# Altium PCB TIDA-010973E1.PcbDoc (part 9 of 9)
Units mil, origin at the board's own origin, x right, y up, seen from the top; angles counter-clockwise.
Board outline 5166 x 3669 mil, 8 copper layers (L01 - TOP, L02 - GND, L03 - SIG, L04 - GND, L05 - PWR, L06 - SIG, L07 - GND, L08 - BOTTOM), stack 61.7 mil thick; 677 components, 493 nets, 2522 pads, 1424 vias.
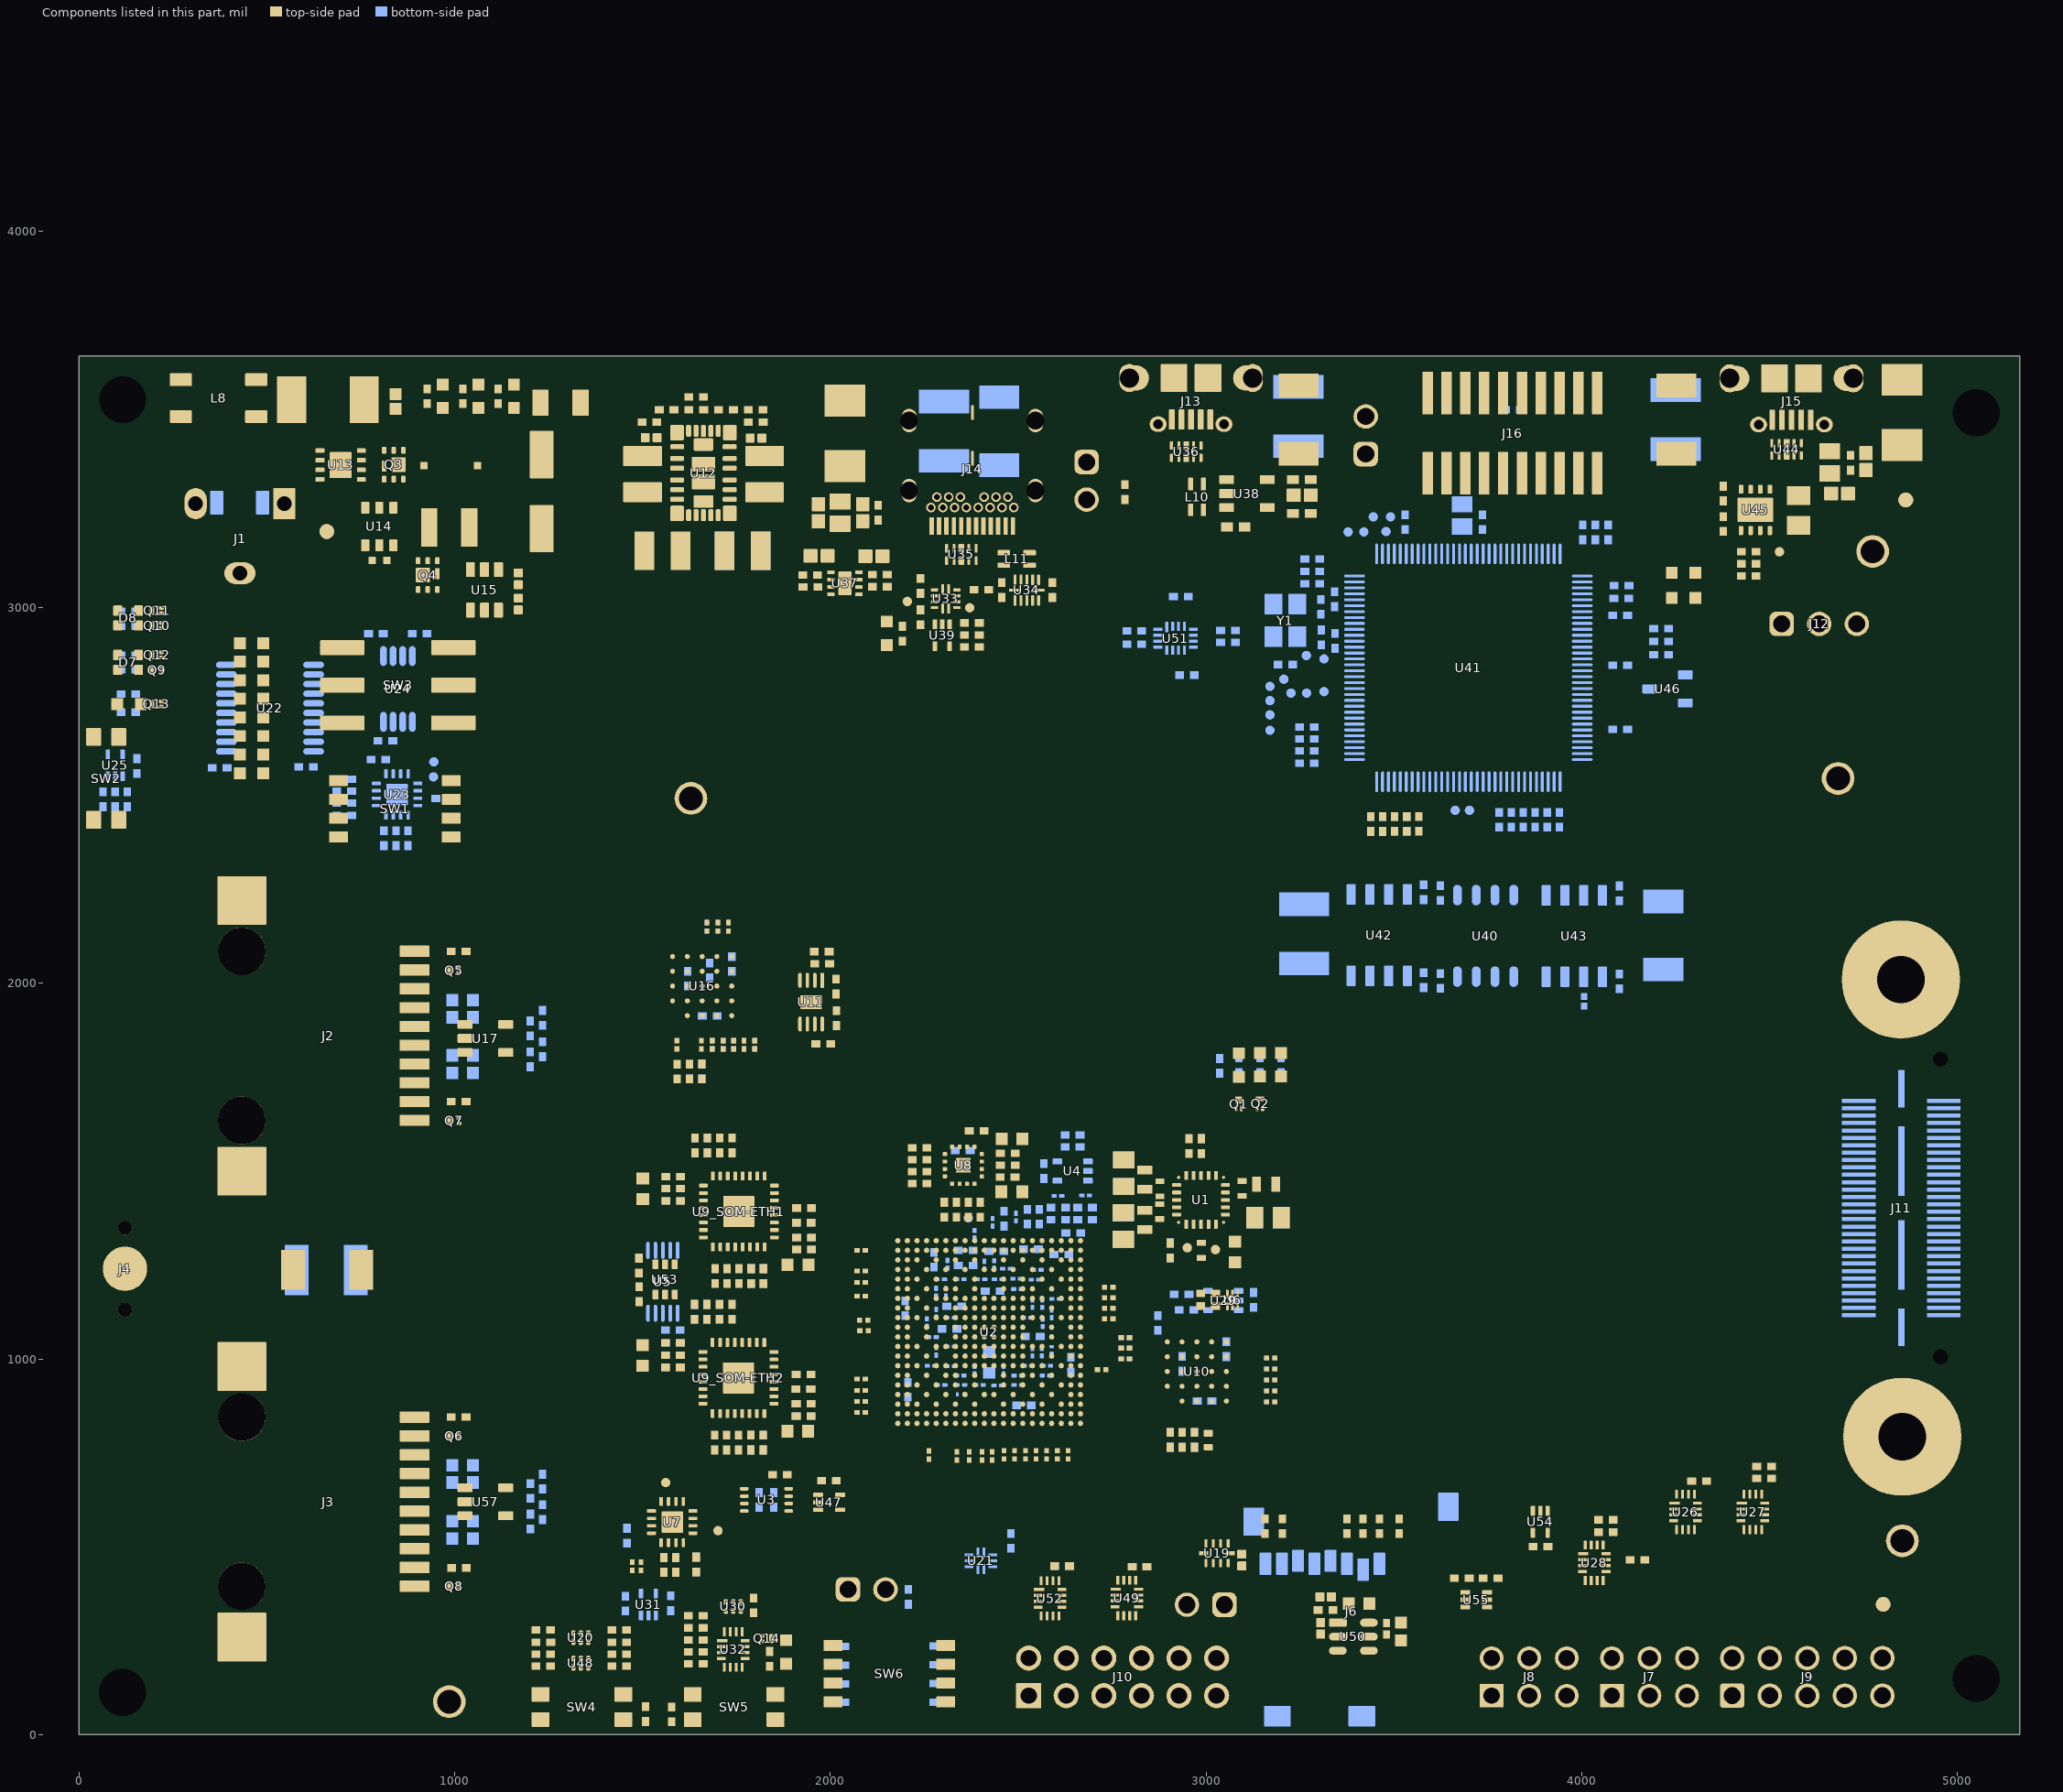
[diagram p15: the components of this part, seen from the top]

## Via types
v1: diameter 18, hole 8, L01 - TOP to L08 - BOTTOM, tented both sides, 1389 vias
v2: diameter 19.68, hole 7.87, L01 - TOP to L08 - BOTTOM, 24 vias
v3: diameter 19.68, hole 7.87, L01 - TOP to L08 - BOTTOM, tented both sides, 11 vias

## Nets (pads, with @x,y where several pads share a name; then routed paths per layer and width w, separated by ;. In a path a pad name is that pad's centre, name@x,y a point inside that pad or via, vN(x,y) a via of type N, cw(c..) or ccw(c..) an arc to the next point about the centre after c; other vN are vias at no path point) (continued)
pads on no net: FID1.1 FID2.1 FID3.1 FID4.1 FID5.1 FID6.1 H1.1 H2.1 J2. J3. J8.6 J10.10 J10.11 J10.12 J11.1 J11.57 J11.MH1 J11.MH2 J14.A2 J14.A3 J14.A8 J14.A10 J14.A11 J14.B2 J14.B3 J14.B8 J14.B10 J14.B11 J16.2 J16.6 J16.8 J16.13 J16.14 J16.15 J16.17 J16.18 J16.19 LBL1.0 MH1.1 MH2.1 MH3.1 MH4.1 Q2.0 Q3.0 Q4.0 Q5.0 Q6.0 Q7.0 Q8.0 Q9.0 Q10.0 Q11.0 Q12.0 Q13.0 Q14.0 SH-J1.0 SH-J2.0 U1.9 U1.15 U2.G1 U2.G2 U2.H1 U2.H2 U2.M1 U2.T3 U2.U17 U2.W3 U2.W4 U2.W5 U2.Y2 U6.5 U7.17@1579.47,565.88 U9_SOM-ETH1.8 U9_SOM-ETH2.8 U10.A2 U10.A3 U10.B1 U10.B5 U10.C5 U12.11 U12.20 U12.21 U12.26 U13.9 U16.A2 U16.A5 U16.B1 U16.B5 U16.C5 U19.4 U19.9 U20.1 U20.5 U23.17@847.12,2502.16 U25.1 U26.11 U26.12 U27.11 U27.12 U30.1 U30.5 U34.6 U34.12 U35.3@2349,3157.44 U35.8@2349,3124.56 U36.1 U36.3@2947.32,3398.13 U36.8@2947.32,3431 U36.10 U37.0 U41.2 U41.5 U41.6 U41.11 U41.12 U41.13 U41.14 U41.15 U41.18 U41.19 U41.20 U41.21 U41.22 U41.23 U41.24 U41.25 U41.27 U41.29 U41.30 U41.31 U41.32 U41.40 U41.41 U41.44 U41.45 U41.46 U41.53 U41.54 U41.56 U41.57 U41.65 U41.67 U41.83 U41.84 U41.85 U41.86 U41.91 U41.92 U41.102 U41.103 U41.104 U41.105 U41.106 U41.107 U41.108 U41.109 U41.110 U41.111 U41.112 U41.116 U41.117 U41.118 U41.119 U41.120 U41.121 U41.123 U41.124 U41.125 U41.126 U41.127 U41.128 U44.1 U44.3@4545,3404.56 U44.8@4545,3437.44 U44.10 U45.7 U45.9@4437.2,3259.64 U45.9@4486.8,3259.64 U50.4 U52.8 U52.9 U52.11 U52.12 U54.1
copper on no net:
  other v2: 697,3354.39 677.32,3379 716.68,3379 697,3403.61

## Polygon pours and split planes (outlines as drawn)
SHIELD_USB on L01 - TOP "L01_-_TOP_NONET_P039" (solid, remove dead copper, shelved, pour order 39): 2156,3665 2156,3211.8 2587,3211.8 2587,3665
SHIELD_USB2 on L01 - TOP "L01_-_TOP_NONET_P033" (solid, remove dead copper, shelved, pour order 33): 2742,3671.99 2742,3442.29 3154,3442.29 3154,3522 3324,3522 3324,3673
SHIELD_XDS on L01 - TOP "L01_-_TOP_NONET_P025" (solid, remove dead copper, shelved, pour order 25): 4161,3668 4161,3666.23 4161,3550 4363,3550 4363,3421 4771,3421 4771,3526 4771,3671.17
EARTH_GND on L01 - TOP "L01_-_TOP_NONET_P016" (solid, remove dead copper, shelved, pour order 16): 0,2291 2,2289 611,2289 611,194 499,194 0,194
VCORE_1V25 on L01 - TOP "L01_-_TOP_NONET_P013" (solid, remove dead copper, shelved, pour order 13): 3173.99,1484.65 3174.63,1484 3225,1484 3225,1346.8 3224.95,1346.75 3224.54,1347.16 3177.74,1347.16 3177.74,1443.2 3176.52,1444.43 3173.86,1444.43
VSYS_1V8 on L01 - TOP "L01_-_TOP_NONET_P012" (solid, remove dead copper, shelved, pour order 12): 2752.02,1553.11 2856.89,1553.11 2857,1553 2856.77,1552.77 2856.77,1491.22 2817.8,1491.22 2817.72,1491.31 2817.72,1507.29 2752.17,1507.29
VSYS_3V3 on L01 - TOP "L01_-_TOP_NONET_P011" (solid, remove dead copper, shelved, pour order 11): 2751,1341 2751.14,1340.86 2817.66,1340.86 2817.66,1356.46 2817.72,1356.53 2856.58,1356.53 2856.58,1292.83 2856.51,1292.77 2853.46,1295.83 2751.48,1295.83
GND on L01 - TOP "L01_-_TOP_NONET_P010" (solid, remove dead copper, shelved, pour order 10): 3041.88,1428.34 3043.1,1427.12 3071.31,1427.12 3084.19,1440 3134,1440 3152,1440 3152,1418 3152,1371 3110,1371 3062.5,1418.5 3041.88,1418.5
GND on L01 - TOP "L01_-_TOP_NONET_P009" (solid, remove dead copper, shelved, pour order 9): 2753,1481 2809,1481 2809,1437 2889.91,1437 2933.27,1425.22 2933.27,1419.37 2906.37,1419.37 2888.81,1406.09 2884.91,1410 2752,1410 2751,1409
NetC92_2 on L01 - TOP "L01_-_TOP_NONET_P004" (solid, remove dead copper, shelved, pour order 4): 1315,3583.39 1360.74,3583.39 1360.74,3433 1557,3433 1557,3376 1315,3376
5V on L01 - TOP "L01_-_TOP_NONET_P002" (solid, remove dead copper, shelved, pour order 2): 1576.51,3292.26 1576.95,3292.69 1636,3292.69 1636,3297 1635,3298 1748.21,3298 1748.21,3268.77 1748.21,3102.79 1752,3099 1748,3095 1575,3095
V_IN on L01 - TOP "L01_-_TOP_NONET_P001" (solid, remove dead copper, shelved, pour order 1): 833,3427 928,3427 928,3164 930,3162 929,3161 864,3161 864,3251 863,3252 863,3305 834,3305 833,3304
V_PLUG on L01 - TOP "L01_-_TOP_NONET_P000" (solid, remove dead copper, shelved, pour order 0): 721.43,3615.39 721.82,3615 798,3615 798,3390 818,3390 818,3333 817,3332 740,3332 740,3470 720,3470
SHIELD_USB on L08 - BOTTOM "L08_-_BOTTOM_NONET_P040" (solid, remove dead copper, shelved, pour order 40): 2156,3665 2156,3211.8 2587,3211.8 2587,3665
SHIELD_USB2 on L08 - BOTTOM "L08_-_BOTTOM_NONET_P035" (solid, remove dead copper, shelved, pour order 35): 2742,3671.99 2742,3442.29 3154,3442.29 3154,3522 3324,3522 3324,3673
SHIELD_XDS on L08 - BOTTOM "L08_-_BOTTOM_NONET_P028" (solid, remove dead copper, shelved, pour order 28): 4161,3668 4161,3666.23 4161,3550 4363,3550 4363,3421 4771,3421 4771,3526 4771,3671.17
EARTH_GND on L08 - BOTTOM "L08_-_BOTTOM_NONET_P020" (solid, remove dead copper, shelved, pour order 20): 0,2291 2,2289 611,2289 611,194 499,194 0,194
NetC92_2 on L08 - BOTTOM "L08_-_BOTTOM_NONET_P003" (solid, remove dead copper, shelved, pour order 3): 1315,3583.39 1315,3376 1884,3376 1884,3483.64 1360.74,3483.64 1360.74,3583.39
GND on L02 - GND "L02_-_GND_NONET_P049" (solid, remove dead copper, shelved, pour order 49): 0,3670 -4,3666 -4,2375 700,2375 700,-4 5162,-4 5166,0 5165,1 5165,3669
SHIELD_USB on L02 - GND "L02_-_GND_NONET_P044" (solid, remove dead copper, shelved, pour order 44): 2156,3665 2156,3211.8 2587,3211.8 2587,3665
SHIELD_USB on L02 - GND "L02_-_GND_NONET_P043" (solid, remove dead copper, shelved, pour order 43): 2156,3665 2156,3211.8 2587,3211.8 2587,3665
SHIELD_USB2 on L02 - GND "L02_-_GND_NONET_P034" (solid, remove dead copper, shelved, pour order 34): 2742,3671.99 2742,3442.29 3154,3442.29 3154,3522 3324,3522 3324,3673
GND_XDS on L02 - GND "L02_-_GND_NONET_P031" (solid, remove dead copper, shelved, pour order 31): 3107,2152.65 3107,3314 4148,3314 4148,3323 4148,3461 4351,3461 4351,3415 4782,3415 4782,3652 4920,3652 4920,3633 4920,3008 4904,3008 4380,3008 4380,2172 4380,2155.74
SHIELD_XDS on L02 - GND "L02_-_GND_NONET_P027" (solid, remove dead copper, shelved, pour order 27): 4161,3668 4161,3666.23 4161,3550 4363,3550 4363,3421 4771,3421 4771,3526 4771,3671.17
EARTH_GND on L02 - GND "L02_-_GND_NONET_P021" (solid, remove dead copper, shelved, pour order 21): 0,2291 2,2289 611,2289 611,194 499,194 0,194
VSYS_3V3 on L04 - GND "L04_-_GND_NONET_P018" (solid, remove dead copper, shelved, pour order 18): 2547,993.2 2552.8,999 2578,999 2578,632.55 1436,632.55 1436,1658 2494.6,1658 2821.92,1377.7 2825,1273 2796,1273 2595.5,1072.5 2595.5,1028.16 2551.16,1028.16 2548,1025 2544.99,1028.01 2544.99,1216.91 2440.11,1216.91 2390.2,1167 2273,1167 2273,1036.62 2353.62,956 2527,956
GND on L04 - GND "L04_-_GND_NONET_P052" (solid, remove dead copper, shelved, pour order 52): 0,3670 -4,3666 -4,2375 700,2375 700,-4 5162,-4 5166,0 5165,1 5165,3669
SHIELD_USB on L04 - GND "L04_-_GND_NONET_P042" (solid, remove dead copper, shelved, pour order 42): 2156,3665 2156,3211.8 2587,3211.8 2587,3665
SHIELD_USB2 on L04 - GND "L04_-_GND_NONET_P037" (solid, remove dead copper, shelved, pour order 37): 2742,3671.99 2742,3442.29 3154,3442.29 3154,3522 3324,3522 3324,3673
GND_XDS on L04 - GND "L04_-_GND_NONET_P030" (solid, remove dead copper, shelved, pour order 30): 3107,2152.65 3107,3259 4148,3259 4148,3323 4148,3461 4351,3461 4351,3415 4782,3415 4782,3652 4920,3652 4920,3633 4920,3008 4904,3008 4380,3008 4380,2172 4380,2155.74
SHIELD_XDS on L04 - GND "L04_-_GND_NONET_P026" (solid, remove dead copper, shelved, pour order 26): 4161,3668 4161,3666.23 4161,3550 4363,3550 4363,3421 4771,3421 4771,3526 4771,3671.17
EARTH_GND on L04 - GND "L04_-_GND_NONET_P023" (solid, remove dead copper, shelved, pour order 23): 0,2291 2,2289 611,2289 611,194 499,194 0,194
GND on L07 - GND "L07_-_GND_NONET_P050" (solid, remove dead copper, shelved, pour order 50): 0,3670 -4,3666 -4,2375 700,2375 700,-4 5162,-4 5166,0 5165,1 5165,3669
SHIELD_USB2 on L07 - GND "L07_-_GND_NONET_P036" (solid, remove dead copper, shelved, pour order 36): 2742,3671.99 2742,3442.29 3154,3442.29 3154,3522 3324,3522 3324,3673
GND_XDS on L07 - GND "L07_-_GND_NONET_P032" (solid, remove dead copper, shelved, pour order 32): 3107,2152.65 3107,3276 4148,3276 4148,3323 4148,3461 4351,3461 4351,3415 4782,3415 4782,3652 4920,3652 4920,3633 4920,3008 4904,3008 4380,3008 4380,2172 4380,2155.74
SHIELD_XDS on L07 - GND "L07_-_GND_NONET_P029" (solid, remove dead copper, shelved, pour order 29): 4161,3668 4161,3666.23 4161,3550 4363,3550 4363,3421 4771,3421 4771,3526 4771,3671.17
EARTH_GND on L07 - GND "L07_-_GND_NONET_P017" (solid, remove dead copper, shelved, pour order 17): 0,2291 2,2289 611,2289 611,194 499,194 0,194
VSYS_3V3 on L05 - PWR "L05_-_PWR_NONET_P054" (solid, remove dead copper, shelved, pour order 54): 2547,993.2 2552.8,999 2578,999 2578,632.55 1436,632.55 1436,1658 2494.6,1658 2821.92,1377.7 2825,1273 2796,1273 2595.5,1072.5 2595.5,1028.16 2551.16,1028.16 2548,1025 2544.99,1028.01 2544.99,1216.91 2440.11,1216.91 2390.2,1167 2273,1167 2273,1036.62 2353.62,956 2527,956
VDD_XDS3V3 on L05 - PWR "L05_-_PWR_NONET_P051" (solid, remove dead copper, shelved, pour order 51): 3107,2152.65 3107,3314 4148,3314 4148,3323 4148,3461 4351,3461 4351,3415 4782,3415 4782,3652 4920,3652 4920,3633 4920,3008 4904,3008 4380,3008 4380,2172 4380,2155.74
VSYS_3V3 on L05 - PWR "L05_-_PWR_NONET_P053" (solid, remove dead copper, shelved, pour order 53): 0,3670 -4,3666 -4,2375 700,2375 700,-4 5162,-4 5166,0 5165,1 5165,3669
5V on L05 - PWR "L05_-_PWR_NONET_P048" (solid, remove dead copper, shelved, pour order 48): 1554.87,3300.19 1554.87,3060.87 1552,3058 1750,2860 2677.53,2860 2809.75,1591 2809.75,1273.75 2804,1268 3198,1268 3198,3089 3198,3396 1607.25,3396 1581.7,3370.45
VSYS_USB_5V on L05 - PWR "L05_-_PWR_NONET_P024" (solid, remove dead copper, shelved, pour order 24): 1783,3192 2113,3192 2113,2827 907,2827 907,3198 1347,3198 1501,3044 1783,3044
VCORE_1V25 on L05 - PWR "L05_-_PWR_NONET_P022" (solid, remove dead copper, shelved, pour order 22): 2287.52,1178.12 2287.64,1178 2332,1178 2332,1177 2345.71,1163.29 2345.71,994.48 2500.15,994.48 2499.15,995.48 2499.15,1179.87 2510.23,1190.95 2538.15,1190.95 2567.35,1161.75 2567.35,1107.82 3017.23,1107.82 3155,1245.59 3155,1406 3272,1406 3272,1073.28 3078.06,879.34 2282.38,879.34
VSYS_3V3 on L06 - SIG "L06_-_SIG_NONET_P055" (solid, remove dead copper, shelved, pour order 55): 2547,993.2 2552.8,999 2578,999 2578,632.55 1436,632.55 1436,1658 2494.6,1658 2821.92,1377.7 2825,1273 2796,1273 2595.5,1072.5 2595.5,1028.16 2551.16,1028.16 2548,1025 2544.99,1028.01 2544.99,1216.91 2440.11,1216.91 2390.2,1167 2273,1167 2273,1036.62 2353.62,956 2527,956

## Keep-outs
Keep-Out Layer:
  text ".Layer_Name" at 577,-858.49 h60

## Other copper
L01 - TOP:
  text ".Layer_Name" at 577,-858.49 h60
L08 - BOTTOM:
  text ".Layer_Name" at 577,-858.49 h60

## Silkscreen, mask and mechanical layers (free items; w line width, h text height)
Top Overlay:
  lines w5: 969,3649 969,3656 1461,3656 1461,3626 ; 1065,3649 1065,3656 ; 1158,3648 1158,3655 ; 1392,3626 1392,3656 ; 1428,3626 1428,3656
  lines w6: 1470,715.78 3245,715.78 3245,1616 1470,1616 1470,715.78
  text "5V" at 1476.5,3569.5 h25 r90
  text "USB0" at 2594.5,3549.5 h25 r90
  text "USB0" at 2741.5,3550.5 h25 r90
  text "VIN" at 1403.5,3547.5 h25 r90
  text "VUSB" at 1440.5,3519.5 h25 r90
  text "XDS110" at 4356.5,3503.5 h25 r90
  text "JTAG" at 4112.5,3368.5 h25 r90
  text "JTAG select" at 3516.5,3322.5 h25 r90
  text "ID" at 2665.5,3202.5 h25
  text "VIN: 5V-32V" at 21.5,3039.5 h30
  text "GND_XDS" at 4691.5,3039.67 h25
  text "USER" at 428.5,2987.5 h25
  text "RUN" at 262.5,2960.5 h25
  text "LED" at 427.5,2948.5 h25
  text "ERR" at 262.5,2840.5 h25
  text "User" at 1100.5,2815.5 h25
  text "1.8V" at 4747.5,2810.5 h25 r90
  text "3.3V" at 4545.5,2801.5 h25 r90
  text "V_HPI" at 4642.33,2779.5 h25 r90
  text "Rorary" at 1100.5,2773.99 h25
  text "Switch" at 1100.5,2733.5 h25
  text "SAFETY" at 162.5,2671.9 h25
  text "ERROR" at 162.5,2634.5 h25
  text "User" at 1100.5,2502.5 h25
  text "Dip" at 1100.5,2461.99 h25
  text "GND" at 4649.5,2426.5 h25
  text "Switch" at 1100.5,2421.5 h25
  text "GND" at 1602.5,2384.5 h25
  text "User" at 34.5,2350.5 h25
  text "Button" at 34.5,2311.5 h25
  text "Port 1" at 702.5,2206.5 h30
  text "1.25V" at 3095.5,1913.5 h25 r90
  text "1.8V" at 3155.5,1914.5 h25 r90
  text "3.3V" at 3213.5,1913.5 h25 r90
  text "TIDA-010973E1" at 2351,1826 h50
  text "U9-ETH1" at 1836.5,1539.5 h25
  text "EARTH_GND" at 262.5,1100.5 h30 r90
  text "U9_ETH2" at 1834.44,1064.92 h25
  text "Port 2" at 689.5,976.5 h30
  text "I2C1" at 2106.5,447.5 h25
  text "SDIO mux" at 2907.5,407.5 h25
  text "GND" at 4830.5,401.5 h25
  text "BOOT MODE" at 2047.5,304.5 h25
  text "GND" at 949.5,176.5 h25
  text "PORZ" at 1161.5,39.5 h25 r90
  text "1" at 2012.5,27.5 h25
  text "0" at 2293.5,28.5 h25
  text "WARMRSTN" at 1956.5,20.5 h25 r90
  text ".Layer_Name" at 577,-858.49 h60
Bottom Overlay:
  text "Host Port Interface" at 5119.5,1177.5 h25 r270
  text ".Layer_Name" at 577,-858.49 h60
Top Paste:
  text ".Layer_Name" at 577,-858.49 h60
Bottom Paste:
  text ".Layer_Name" at 577,-858.49 h60
Top Solder:
  text ".Layer_Name" at 577,-858.49 h60
  text ".Layer_Name" at 577,-858.49 h60
Bottom Solder:
  text ".Layer_Name" at 577,-858.49 h60
Drill Guide:
  text ".Layer_Name" at 577,-858.49 h60
M1 Board Outline:
  lines w10: 0,0 0,3670 5165,3669 5166,0 0,0
  text ".Layer_Name" at 577,-858.49 h60
M2 Board Dimensions:
  rectangle: 0,-275 125,-150
  rectangle: 125,-400 500,-275
  lines w7: 0,-275 1000,-275 ; 125,-400 125,-150 ; 250,-400 250,-150 ; 500,-400 500,-150 ; 750,-400 750,-150 ; 0,-400 1000,-400 1000,-150 0,-150 0,-400
  text ".Layer_Name" at 577,-858.49 h60
M3 3D STEP Top:
  text ".Layer_Name" at 577,-858.49 h60
M4 3D STEP Bottom:
  text ".Layer_Name" at 577,-858.49 h60
M5 Assembly Top:
  lines w10: -292,-930.17 6308,-930.17 ; -292,-726.83 6310,-726.83 ; -292,-523.5 -292,-1133.5 3713,-1133.5 6310,-1133.5 6310,-523.5 -291.5,-523.5 -291.5,-1133.5 1284,-1133.5 ; 2173,-1133.5 2173,-523.5 ; 3440,-726.83 3440,-523.5 ; 4280,-726.83 4280,-523.5 ; 4902,-1140 4902,-937.17
  text "COMPONENTS MARKED 'DNP' SHOULD NOT BE POPULATED." at 1153.5,-318.5 h60
  text "ASSEMBLY VARIANT:" at 1153,-434 h60
  text ".VariantName" at 2189,-434 h60
  text "PCB VIEWED FROM TOP SIDE" at -228.5,-655.67 h60
  text "BOARD #:" at 2248,-655.67 h60
  text ".PRJ_Number" at 2793.5,-655.67 h60
  text "REV:" at 3638,-655.67 h60
  text ".PCB_Rev" at 3929.5,-655.67 h60
  text "SVN REV:" at 4476,-655.67 h60
  text ".VersionControl_RevNumber" at 4982,-655.67 h60
  text "TID #:" at 2248,-859 h60
  text ".TID" at 2793.5,-859 h60
  text "PLOT NAME =" at -228.5,-1064.34 h60
  text ".plot_File_Name" at 577,-1064.34 h60
  text "GENERATED    :" at 2250,-1064.34 h60
  text ".Print_Date" at 3119.5,-1064.34 h60
  text ".Print_Time" at 3848.5,-1064.34 h60
  text "TEXAS INSTRUMENTS" at 5113,-1064.34 h60
M6 Assembly Bottom:
  lines w10: -292.5,-727.33 6309.5,-727.33 ; -290.5,-930.67 6309.5,-930.67 ; 1115.5,-1140.5 1115.5,-937.67 ; 1737.5,-727.33 1737.5,-524 ; 2577.5,-727.33 2577.5,-524 ; 3844.5,-1134 3844.5,-524 ; 4733.5,-1134 6309,-1134 6309,-524 -292.5,-524 -292.5,-1134 2304.5,-1134 6309.5,-1134 6309.5,-524
  text "COMPONENTS MARKED 'DNP' SHOULD NOT BE POPULATED." at 6102,-318 h60
  text ".VariantName" at 5058,-434 h60
  text "ASSEMBLY VARIANT:" at 6097,-434 h60
  text ".VersionControl_RevNumber" at 1035.5,-656.17 h60
  text "SVN REV:" at 1541.5,-656.17 h60
  text ".PCB_Rev" at 2088,-656.17 h60
  text "REV:" at 2379.5,-656.17 h60
  text ".PRJ_Number" at 3224,-656.17 h60
  text "BOARD #:" at 3769.5,-656.17 h60
  text "PCB VIEWED FROM BOTTOM SIDE" at 6246,-656.17 h60
  text ".TID" at 3224,-859.5 h60
  text "TID #:" at 3769.5,-859.5 h60
  text "TEXAS INSTRUMENTS" at 904.5,-1064.84 h60
  text ".Print_Time" at 2169,-1064.84 h60
  text ".Print_Date" at 2898,-1064.84 h60
  text "GENERATED    :" at 3767.5,-1064.84 h60
  text ".plot_File_Name" at 5440.5,-1064.84 h60
  text "PLOT NAME =" at 6246,-1064.84 h60
M9 Title Sheet:
  drawing of 57 lines, arcs and shapes, not listed
  text "1" at 739.84,8036.5 h70
  text "2" at 3235.5,8036.5 h70
  text "3" at 5724.84,8036.5 h70
  text "4" at 8231.51,8036.5 h70
  text "5" at 10730.5,8036.5 h70
  text "6" at 13235.5,8036.5 h70
  text "A" at -416.5,6893.5 h70
  text "A" at 14383.5,6893.5 h70
  text "B" at -416.5,4513.5 h70
  text "B" at 14383.5,4513.5 h70
  text "C" at -416.5,2138.5 h70
  text "C" at 14383.5,2138.5 h70
  text "PROJECT TITLE:" at 11343.5,277.5 h45
  text ".PRJ_Title" at 11393.5,144.17 h70
  text "DESIGNED FOR:" at 11343.5,-23.5 h45
  text ".PRJ_Customer" at 11393.5,-163.5 h70
  text "D" at -416.5,-231.5 h70
  text "D" at 14383.5,-231.5 h70
  text "FILE NAME:" at 11343.5,-323.5 h45
  text ".PCB_File_Name_No_Path" at 11393.5,-443.5 h70
  text "Texas Instruments (TI) and/or its licensors do not warrant the accuracy or completeness of this specification" at 6374,-605.34 h45
  text "ENGINEER:" at 11343.5,-613.5 h45
  text "LAYOUT BY:" at 12848.5,-613.5 h45
  text "or any information contained therein. TI and/or its licensors do not warrant that this design will meet" at 6329.01,-718 h45
  text ".PRJ_Engineer" at 11393.5,-768.49 h70
  text ".PCB_Layout" at 12899,-768.49 h70
  text "the specifications, will be suitable for your application or fit for any particular purpose, or will operate in" at 6329.01,-830.67 h45
  text ".Layer_Name" at 577,-858.49 h60
  text "ALTIUM DESIGNER VERSION:" at 12848.5,-923.5 h45
  text "an implementation. TI and/or its licensors do not warrant that the design is production worthy. You should" at 6329.01,-943.33 h45
  text "completely validate and test your design implementation to confirm the system functionality for your application." at 6374,-1056 h45
  text ".print_Scale" at 11393.5,-1056.83 h70
  text ".Application_BuildNumber" at 12899,-1056.83 h70
  text "1" at 739.84,-1263.5 h70
  text "2" at 3235.5,-1263.5 h70
  text "3" at 5724.84,-1263.5 h70
  text "4" at 8231.51,-1263.5 h70
  text "5" at 10730.5,-1263.5 h70
  text "6" at 13235.5,-1263.5 h70
M10 Fab Notes:
  drawing of 189 lines, arcs and shapes, not listed
  text "DESIGN INFORMATION" at 12382.02,6356.17 h60
  text "MIN. TRACK WIDTH:" at 11737.46,6224.05 h60
  text "5" at 12833.7,6224.05 h60
  text "MIL" at 12988.46,6224.05 h60
  text "5" at 12830,6110 h60
  text "MIN. CLEARANCE:" at 11737.46,6099.92 h60
  text "MIL" at 12988.46,6099.92 h60
  text "MIN. VIA PAD SIZE:" at 11737.46,5975.8 h60
  text "20" at 12803.71,5975.8 h60
  text "MIL" at 12988.46,5975.8 h60
  text "0.05mm (2MIL)" at 12432.46,5845.9 h60
  text "MINIMUM ANNULAR RING" at 11408.23,5837.67 h60
  text "EXTERNAL" at 13140.46,5837.67 h60
  text "PER" at 11608.23,5727.55 h60
  text "IPC-D-275 CLASS 2 LEVEL C" at 11828.23,5727.54 h60
  text "MIL, HOLES" at 13316.46,5627.07 h60
  text "+/-" at 12924,5618.48 h60
  text "+/-" at 13778,5618.48 h60
  text "REGISTRATION TOLERANCES:" at 11408.23,5617.42 h60
  text "METAL" at 12608,5617.42 h60
  text "5" at 13184.2,5617.42 h60
  text "3" at 14017.2,5617.42 h60
  text "MIL" at 14133.46,5617.42 h60
  text "HOLE SIZE TOLERANCE (UNLESS OTHERWISE SPECIFIED):" at 11408.23,5519.1 h60
  text "+/-" at 13778,5516.23 h60
  text "3" at 14017.2,5515.17 h60
  text "MIL" at 14133.46,5515.17 h60
  text "MATERIAL:" at 11333.46,5377.52 h60
  text "FR-4 High Tg" at 12319.9,5249 h60
  text "X" at 12175.46,5241.01 h60
  text "FR-408" at 11754.46,5236.49 h60
  text "OTHER" at 13242.46,5236.49 h60
  text "62 MIL (1.6mm) +/-10%" at 12074.56,5093.46 h60
  text "X" at 11954.46,5091.01 h60
  text "THICKNESS:" at 11408.23,5085.24 h60
  text "OTHER" at 13359.46,5085.24 h60
  text "TOLERANCE:" at 11408.23,4946.92 h60
  text "X" at 12256.46,4946.92 h60
  text "ANSI IPC-6012 TYPE 3 CLASS 2" at 12434.48,4946.92 h60
  text "OTHER +/-" at 12434.46,4802.73 h60
  text "BOW & TWIST:" at 11408.23,4657.54 h60
  text "X" at 12256.46,4657.54 h60
  text "ANSI IPC-6012 TYPE 3 CLASS 2" at 12434.48,4657.54 h60
  text "OTHER +/-" at 12434.46,4510.85 h60
  text "DRILLING:" at 11333.46,4380.23 h60
  text "NC_DRILL FILES" at 13094.46,4275.04 h60
  text "REFERENCE:" at 11408.23,4271.1 h60
  text "X" at 12065.46,4271.01 h60
  text "AS SHOWN" at 12243.46,4271.1 h60
  text "X" at 12966.46,4271.1 h60
  text "OTHER" at 13392.46,4128.85 h60
  text "PTH COPPER THICKNESS:" at 11407.91,4125.32 h60
  text "X" at 12547.14,4125.32 h60
  text "20-30 um" at 12675.14,4125.32 h60
  text "BOARD FINISH:" at 11333.46,3977.73 h60
  text "SILKSCREEN:" at 11488.68,3867.6 h60
  text "X" at 12446.46,3867.6 h60
  text "TOP" at 12563.46,3867.6 h60
  text "X" at 12956.46,3867.6 h60
  text "BOTTOM" at 13074.46,3867.6 h60
  text "SILKSCREEN COLOR:" at 11488.68,3712.41 h60
  text "X" at 12445.46,3712.41 h60
  text "WHITE" at 12563.46,3712.41 h60
  text "OTHER" at 13074.46,3712.41 h60
  text "X" at 12576.46,3568.96 h60
  text "GREEN" at 12694.46,3568.96 h60
  text "OTHER" at 13312.46,3568.96 h60
  text "SOLDER RESIST COLOR:" at 11488.68,3562.1 h60
  text "X" at 12576.46,3414.71 h60
  text "MATTE" at 12694.46,3414.71 h60
  text "SEMI-GLOSS" at 13312,3414.07 h60
  text "IMMERSION GOLD (ENIG)" at 12394.46,3241.94 h60
  text "ENEPIG" at 13732,3234.72 h60
  text "SURFACE FINISH:" at 11333.46,3233.72 h60
  text "X" at 12216.46,3233.72 h60
  text "IMM. TIN/SILVER OR EQUIV" at 11663,3096.4 h60
  text "OTHER" at 13094.46,3092.47 h60
  text "ARRAY/PANEL:" at 11333.46,2937.09 h60
  text "CUT AND TRIM PER M1 BOARD OUTLINE" at 12394.46,2928.87 h60
  text "N.C. ROUTE" at 12394.46,2792.9 h60
  text "X" at 13082.46,2792.9 h60
  text "V. SCORE" at 13260.46,2792.9 h60
  text "CERTIFICATION:" at 11333.46,2663.77 h60
  text "MATERIALS AND WORKMANSHIP FOR ALL PCBS" at 12058.46,2663.77 h60
  text "TO MEET OR EXCEED THE REQUIREMENTS OF:" at 12058.46,2569.71 h60
  text "X" at 11695.97,2441.08 h60
  text "ANSI IPC-A-600F CLASS ->" at 11823.96,2441.08 h60
  text "X" at 13471.97,2441.08 h60
  text "2" at 13581.96,2441.08 h60
  text "1" at 13266.96,2439.58 h60
  text "3" at 13935.96,2439.58 h60
  text "X" at 12507.97,2293.39 h60
  text "RoHS" at 12635.96,2293.39 h60
  text "OTHER" at 13280.36,2293.39 h60
  text "PER ORDER" at 13677.42,2293.39 h60
  text "ALL BOARDS MUST MEET OR EXCEED UL94-V0 REQUIREMENTS." at 11361,2139.57 h60
  text "PCB MUST BEAR THE UL94V-0 UL REGISTERED MATERIAL ID NUMBER" at 11361,2023.5 h60
  text "ADDITIONAL REQUIREMENTS:" at 11103.46,1884.71 h60
  text "MICROSECTION:" at 11178.23,1777.58 h60
  text "YES" at 12083.96,1777.58 h60
  text "REQUIRED" at 13175.46,1602.62 h60
  text "BARE BOARD ELEC. TEST:" at 11408.23,1599.76 h60
  text "NONE" at 12713.96,1599.76 h60
  text "X" at 13057.46,1599.76 h60
  text "PER ORDER" at 13767.46,1599.76 h60
  text "XX MIL VIAS REQUIRE NON-CONDUCTIVE FILL AND PLANARIZE" at 11576.38,1394.82 h59
  text "XX MIL VIAS REQUIRE CONDUCTIVE FILL AND PLANARIZE" at 11584.38,1290.84 h60
  text "OUTER XX MIL TRACES REQUIRE 50 OHM SINGLE-ENDED IMPEDANCE" at 11583.39,1127.46 h58
  text "LAYER 2 & 3 (INNER LAYERS) XX MIL WIDE, XX MIL SPACE / TRACES REQUIRE 100 OHM DIFFERENTIAL IMPEDANCE" at 11575.39,891.74 h60
  text ".Layer_Name" at 577,-858.49 h60
M11 Gerber Information:
  lines w10: -292,-930.17 6308,-930.17 ; -292,-726.83 6310,-726.83 ; -292,-523.5 -292,-1133.5 3713,-1133.5 6310,-1133.5 6310,-523.5 -291.5,-523.5 -291.5,-1133.5 1284,-1133.5 ; 2173,-1133.5 2173,-523.5 ; 3440,-726.83 3440,-523.5 ; 4280,-726.83 4280,-523.5 ; 4902,-1140 4902,-937.17
  text "ALL ARTWORK VIEWED FROM TOP SIDE" at -228.5,-655.67 h60
  text "BOARD #:" at 2248,-655.67 h60
  text ".PRJ_Number" at 2793.5,-655.67 h60
  text "REV:" at 3638,-655.67 h60
  text ".PCB_Rev" at 3929.5,-655.67 h60
  text "SVN REV:" at 4476,-655.67 h60
  text ".VersionControl_RevNumber" at 4982,-655.67 h60
  text "LAYER NAME =" at -228.5,-858.49 h60
  text "TID #:" at 2248,-859 h60
  text ".TID" at 2793.5,-859 h60
  text "PLOT NAME =" at -228.5,-1064.34 h60
  text ".plot_File_Name" at 577,-1064.34 h60
  text "GENERATED    :" at 2250,-1064.34 h60
  text ".Print_Date" at 3119.5,-1064.34 h60
  text ".Print_Time" at 3848.5,-1064.34 h60
  text "TEXAS INSTRUMENTS" at 5113,-1064.34 h60
M12 Stackup:
  drawing of 577 lines, arcs and shapes, not listed
  text "Layer" at 7825.18,11059.01 h60
  text "Name" at 8235.09,11059.01 h60
  text "Material" at 9564.71,11059.01 h60
  text "Thickness" at 10934.31,11059.01 h60
  text "Constant" at 11584.14,11059.01 h60
  text "Board Layer Stack" at 12154,11059.01 h60
  text "Top Overlay" at 8235.09,10939.01 h60
  text "Top Solder" at 8235.09,10819.01 h60
  text "Solder Resist" at 9564.71,10819.01 h60
  text "0.40mil" at 10934.31,10819.01 h60
  text "3.5" at 11584.14,10819.01 h60
  text "Top Surface Finish" at 8235.09,10699.01 h60
  text "Nickel, Gold" at 9564.71,10699.01 h60
  text "0.15mil" at 10934.31,10699.01 h60
  text "1" at 7825.18,10579.01 h60
  text "L01 - TOP" at 8235.09,10579.01 h60
  text "1.80mil" at 10934.31,10579.01 h60
  text "Dielectric1" at 8235.09,10459.01 h60
  text "1080 RC64" at 9564.71,10459.01 h60
  text "2.75mil" at 10934.31,10459.01 h60
  text "4.2" at 11584.14,10459.01 h60
  text "2" at 7825.18,10339.01 h60
  text "L02 - GND" at 8235.09,10339.01 h60
  text "CF-004" at 9564.71,10339.01 h60
  text "1.20mil" at 10934.31,10339.01 h60
  text "Dielectric 2" at 8235.09,10219.01 h60
  text "3.5mil Core" at 9564.71,10219.01 h60
  text "3.50mil" at 10934.31,10219.01 h60
  text "4.5" at 11584.14,10219.01 h60
  text "3" at 7825.18,10099.01 h60
  text "L03 - SIG" at 8235.09,10099.01 h60
  text "0.60mil" at 10934.31,10099.01 h60
  text "Dielectric 3" at 8235.09,9979.01 h60
  text "1080 RC64 + 7628 RC43" at 9564.71,9979.01 h60
  text "9.80mil" at 10934.31,9979.01 h60
  text "4.1" at 11584.14,9979.01 h60
  text "IMPEDANCE SPECIFICATIONS:" at 4683.74,9946.26 h35
  text "4" at 7825.18,9859.01 h60
  text "L04 - GND" at 8235.09,9859.01 h60
  text "1.20mil" at 10934.31,9859.01 h60
  text "Z0 = 50R" at 5254.61,9828.15 h35
  text "Zdiff = 100R" at 5904.21,9828.15 h35
  text "TYPE" at 4723.11,9788.78 h35
  text "line width" at 5215.24,9749.41 h35
  text "line width / space" at 5805.79,9749.41 h35
  text "Dielectric 4" at 8235.09,9739.01 h60
  text "20mil Core" at 9564.71,9739.01 h60
  text "20.00mil" at 10934.31,9739.01 h60
  text "4.5" at 11584.14,9739.01 h60
  text "LAYER 1" at 4683.74,9631.3 h35
  text "4.3 MIL" at 5254.61,9631.3 h35
  text "3.50 / 7.6 MIL" at 5884.53,9631.3 h35
  text "5" at 7825.18,9619.01 h60
  text "L05 - PWR" at 8235.09,9619.01 h60
  text "1.20mil" at 10934.31,9619.01 h60
  text "LAYER 2" at 4683.74,9513.19 h35
  text "REF GND" at 5254.61,9513.19 h35
  text "REF GND" at 5884.53,9513.19 h35
  text "Dielectric 5" at 8235.09,9499.01 h60
  text "1080 RC64 + 7628 RC43" at 9564.71,9499.01 h60
  text "9.80mil" at 10934.31,9499.01 h60
  text "4.1" at 11584.14,9499.01 h60
  text "LAYER 3" at 4683.74,9395.08 h35
  text "4.5 MIL" at 5254.61,9395.08 h35
  text "3.50 / 6 MIL" at 5884.53,9395.08 h35
  text "6" at 7825.18,9379.01 h60
  text "L06 - SIG" at 8235.09,9379.01 h60
  text "0.60mil" at 10934.31,9379.01 h60
  text "LAYER 4" at 4683.74,9276.97 h35
  text "Dielectric 6" at 8235.09,9259.01 h60
  text "3.5mil Core" at 9564.71,9259.01 h60
  text "3.50mil" at 10934.31,9259.01 h60
  text "4.5" at 11584.14,9259.01 h60
  text "LAYER 5" at 4683.74,9158.86 h35
  text "7" at 7825.18,9139.01 h60
  text "L07 - GND" at 8235.09,9139.01 h60
  text "CF-004" at 9564.71,9139.01 h60
  text "1.20mil" at 10934.31,9139.01 h60
  text "LAYER 6" at 4683.74,9040.75 h35
  text "4.5 MIL" at 5254.61,9040.75 h35
  text "3.50 / 6 MIL" at 5884.53,9040.75 h35
  text "Dielectric 7" at 8235.09,9019.01 h60
  text "1080 RC64" at 9564.71,9019.01 h60
  text "2.75mil" at 10934.31,9019.01 h60
  text "4.2" at 11584.14,9019.01 h60
  text "LAYER 7" at 4683.74,8926.26 h35
  text "REF GND" at 5254.61,8922.64 h35
  text "REF GND" at 5884.53,8922.64 h35
  text "8" at 7825.18,8899.01 h60
  text "L08 - BOTTOM" at 8235.09,8899.01 h60
  text "1.80mil" at 10934.31,8899.01 h60
  text "LAYER 8" at 4683.74,8808.15 h35
  text "4.3 MIL" at 5254.61,8808.15 h35
  text "3.50 / 7.6 MIL" at 5884.53,8806.34 h35
  text "Bottom Surface Finish" at 8235.09,8779.01 h60
  text "Nickel, Gold" at 9564.71,8779.01 h60
  text "0.15mil" at 10934.31,8779.01 h60
  text "Bottom Solder" at 8235.09,8659.01 h60
  text "Solder Resist" at 9564.71,8659.01 h60
  text "0.40mil" at 10934.31,8659.01 h60
  text "3.5" at 11584.14,8659.01 h60
  text "Bottom Overlay" at 8235.09,8539.01 h60
  text ".Layer_Name" at 577,-858.49 h60
M13 Component Bodies Top:
  text ".Layer_Name" at 577,-858.49 h60
M14 Component Bodies Bottom:
  text ".Layer_Name" at 577,-858.49 h60
M15 Courtyards Top:
  text ".Layer_Name" at 577,-858.49 h60
M16 Courtyards Bottom:
  text ".Layer_Name" at 577,-858.49 h60
Drill Drawing:
  drawing of 160 lines, arcs and shapes, not listed
  text "Symbol" at 8182.41,6229.33 h72
  text "Quantity" at 8482.78,6229.33 h72
  text "Finished Hole Size" at 8814.66,6229.33 h72
  text "Plated" at 9450.86,6229.33 h72
  text "Hole Type" at 9709.77,6229.33 h72
  text "Drill Layer Pair" at 10084.73,6229.33 h72
  text "Hole Tolerance" at 10822.29,6229.33 h72
  text "2" at 8482.78,6105.31 h60
  text "38.19mil (0.970mm)" at 8814.66,6105.31 h60
  text "NPTH" at 9450.86,6105.31 h60
  text "Round" at 9709.77,6105.31 h60
  text "L01 - TOP - L08 - BOTTOM" at 10084.73,6105.31 h60
  text "2" at 8482.78,5981.28 h60
  text "40.16mil (1.020mm)" at 8814.66,5981.28 h60
  text "NPTH" at 9450.86,5981.28 h60
  text "Round" at 9709.77,5981.28 h60
  text "L01 - TOP - L08 - BOTTOM" at 10084.73,5981.28 h60
  text "4" at 8482.78,5857.25 h60
  text "125.00mil (3.175mm)" at 8814.66,5857.25 h60
  text "NPTH" at 9450.86,5857.25 h60
  text "Round" at 9709.77,5857.25 h60
  text "L01 - TOP - L08 - BOTTOM" at 10084.73,5857.25 h60
  text "4" at 8482.78,5733.23 h60
  text "126.77mil (3.220mm)" at 8814.66,5733.23 h60
  text "NPTH" at 9450.86,5733.23 h60
  text "Round" at 9709.77,5733.23 h60
  text "L01 - TOP - L08 - BOTTOM" at 10084.73,5733.23 h60
  text "35" at 8482.78,5609.2 h60
  text "7.87mil (0.200mm)" at 8814.66,5609.2 h60
  text "PTH" at 9450.86,5609.2 h60
  text "Round" at 9709.77,5609.2 h60
  text "L01 - TOP - L08 - BOTTOM" at 10084.73,5609.2 h60
  text "1389" at 8482.78,5485.17 h60
  text "8.00mil (0.203mm)" at 8814.66,5485.17 h60
  text "PTH" at 9450.86,5485.17 h60
  text "Round" at 9709.77,5485.17 h60
  text "L01 - TOP - L08 - BOTTOM" at 10084.73,5485.17 h60
  text "A" at 8157.16,5475.18 h55.12
  text "14" at 8482.78,5361.15 h60
  text "15.75mil (0.400mm)" at 8814.66,5361.15 h60
  text "PTH" at 9450.86,5361.15 h60
  text "Round" at 9709.77,5361.15 h60
  text "L01 - TOP - L08 - BOTTOM" at 10084.73,5361.15 h60
  text "24" at 8482.78,5237.12 h60
  text "43.31mil (1.100mm)" at 8814.66,5237.12 h60
  text "PTH" at 9450.86,5237.12 h60
  text "Round" at 9709.77,5237.12 h60
  text "L01 - TOP - L08 - BOTTOM" at 10084.73,5237.12 h60
  text "21" at 8482.78,5113.09 h60
  text "45.28mil (1.150mm)" at 8814.66,5113.09 h60
  text "PTH" at 9450.86,5113.09 h60
  text "Round" at 9709.77,5113.09 h60
  text "L01 - TOP - L08 - BOTTOM" at 10084.73,5113.09 h60
  text "5" at 8482.78,4989.07 h60
  text "63.00mil (1.600mm)" at 8814.66,4989.07 h60
  text "PTH" at 9450.86,4989.07 h60
  text "Round" at 9709.77,4989.07 h60
  text "L01 - TOP - L08 - BOTTOM" at 10084.73,4989.07 h60
  text "2" at 8482.78,4865.04 h60
  text "125.98mil (3.200mm)" at 8814.66,4865.04 h60
  text "PTH" at 9450.86,4865.04 h60
  text "Round" at 9709.77,4865.04 h60
  text "L01 - TOP - L08 - BOTTOM" at 10084.73,4865.04 h60
  text "4" at 8482.78,4741.01 h60
  text "25.59mil (0.650mm)" at 8814.66,4741.01 h60
  text "PTH" at 9450.86,4741.01 h60
  text "Slot" at 9709.77,4741.01 h60
  text "L01 - TOP - L08 - BOTTOM" at 10084.73,4741.01 h60
  text "3" at 8482.78,4616.99 h60
  text "39.37mil (1.000mm)" at 8814.66,4616.99 h60
  text "PTH" at 9450.86,4616.99 h60
  text "Slot" at 9709.77,4616.99 h60
  text "L01 - TOP - L08 - BOTTOM" at 10084.73,4616.99 h60
  text "4" at 8482.78,4492.96 h60
  text "47.24mil (1.200mm)" at 8814.66,4492.96 h60
  text "PTH" at 9450.86,4492.96 h60
  text "Slot" at 9709.77,4492.96 h60
  text "L01 - TOP - L08 - BOTTOM" at 10084.73,4492.96 h60
  text "4" at 8482.78,4368.93 h60
  text "51.18mil (1.300mm)" at 8814.66,4368.93 h60
  text "PTH" at 9450.86,4368.93 h60
  text "Slot" at 9709.77,4368.93 h60
  text "L01 - TOP - L08 - BOTTOM" at 10084.73,4368.93 h60
  text "1517 Total" at 8482.78,4244.91 h60
  text "Slot definitions :" at 8182.41,4158.09 h60
  text "Routed Path Length" at 8631.85,4158.09 h60
  text "= Calculated from tool start centre position to tool end centre position." at 9170.2,4158.09 h60
  text "Hole Length" at 8631.85,4108.48 h60
  text "= Routed Path Length + Tool Size = Slot length as defined in the PCB layout" at 8970.9,4108.48 h60
  text ".Layer_Name" at 577,-858.49 h60
M17 Embedded Cavity:
  text ".Layer_Name" at 577,-858.49 h60
M18 Embedded Assembly:
  text ".Layer_Name" at 577,-858.49 h60
M19 Embedded Keepout:
  text ".Layer_Name" at 577,-858.49 h60

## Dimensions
0,-400 to 1000,-400 on M2 Board Dimensions
0,0 to 0,3669 on M2 Board Dimensions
